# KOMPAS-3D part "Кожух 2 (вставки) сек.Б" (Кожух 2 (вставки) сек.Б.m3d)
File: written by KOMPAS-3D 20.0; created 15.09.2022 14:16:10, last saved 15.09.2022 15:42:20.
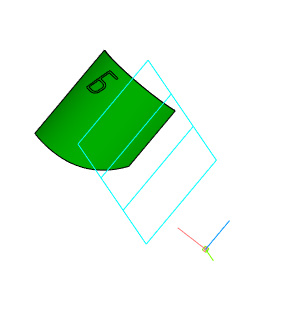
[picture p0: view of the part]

Document properties: Полное имя файла: D:\YAKOVLEV\ПРОЕКТЫ\ДЦ-2. ДП-7 Газопровод Окожушивание\ПРОБА Соединение труб. Окожушивание\Кожух 2 (вставки) сек.Б.m3d

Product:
- Part/product: Кожух 2 (вставки) сек.Б
    Материал: Сталь 45  ГОСТ 1050-2013 (density 7810 kg/m3)
    Масса: 153.619

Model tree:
1. Эскиз:1  (with: Смещенная плоскость:1, Обечайка:1)  (labels: Кожух 2 (вставки))
2. Обечайка:1  (labels: Кожух 1 (трубы); Кожух 2 (вставки))
     Расстояние 1 = 823.908
3. Сгиб(1) - Обечайка:1
     Радиус сгиба = 530; Коэффициент = 0.5; Величина сгиба = 10; Зазор = 0.01; Угол = 180; Параметр U, % = 11; Длина = 366.31
4. Касательная плоскость:1  (with: Обечайка:1)
5. Разогнуть:1  (with: Обечайка:1)
6. Смещенная плоскость:1  (with: Обечайка:1)
     Расстояние = 0.1
7. Эскиз:3  (with: Обечайка:1)
8. Вырез в листовом теле:3
     Глубина выреза = 100
9. Элемент выдавливания:1
     Расстояние 2 = 20
10. Эскиз:4  (with: Обечайка:1, Вырез в листовом теле:3)
11. Вырез в листовом теле:4
     Глубина выреза = 100
12. Эскиз:5  (with: Обечайка:1)
13. Вырез в листовом теле:5
     Глубина выреза = 10
14. Эскиз:6  (with: Обечайка:1)
15. Вырез в листовом теле:6
     Глубина выреза = 0.1
16. Фаска:1  (with: Обечайка:1, Вырез в листовом теле:5)
     Угол = 20; Длина 1 = 14; Длина 2 = 5.09558
17. Согнуть:1  (with: Обечайка:1)
18. Развертка  (labels: Сталь 45  ГОСТ 1050-2013)

Expressions: v172*2
Referenced files in D:\YAKOVLEV\ПРОЕКТЫ\ДЦ-2. ДП-7 Газопровод Окожушивание\ПРОБА Соединение труб. Окожушивание\: Соединение труб. Окожушивание -2.a3d
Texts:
  Соединение труб. Окожушивание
